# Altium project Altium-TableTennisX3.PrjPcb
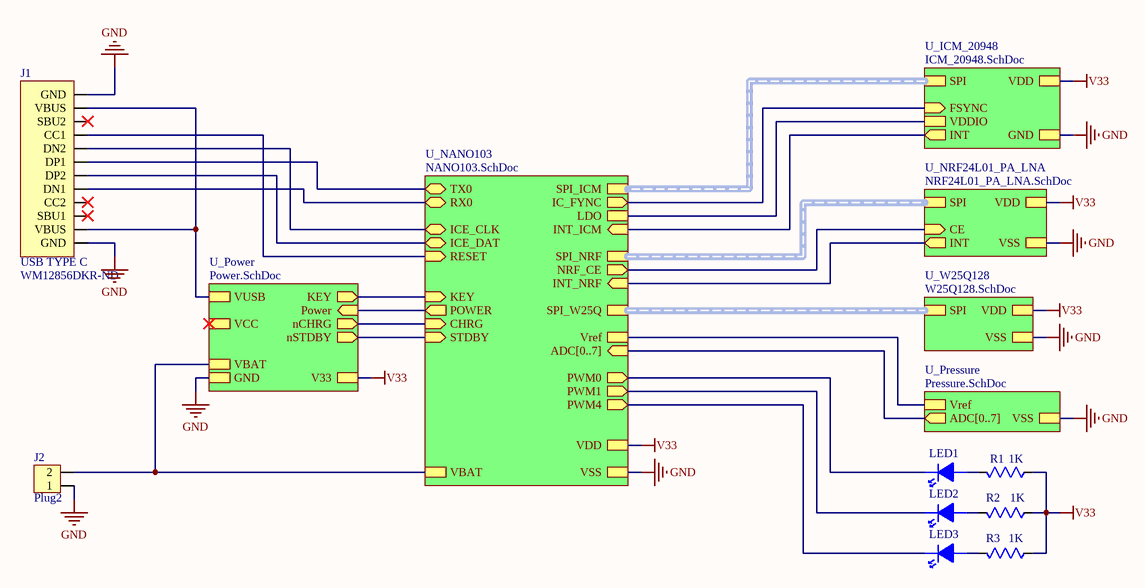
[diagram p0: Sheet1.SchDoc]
7 sheets, 62 parts. Net scope: hierarchical (ports join the sheet entries above them; power ports are global).
Board files: PCB1.PcbDoc, PCB2_bak.PcbDoc, PCB2.PcbDoc
Sheets:
  Sheet1.SchDoc
    U_Power = Power.SchDoc
    U_W25Q128 = W25Q128.SchDoc
    U_ICM_20948 = ICM_20948.SchDoc
    U_NRF24L01_PA_LNA = NRF24L01_PA_LNA.SchDoc
    U_NANO103 = NANO103.SchDoc
    U_Pressure = Pressure.SchDoc

## Sheet Sheet1.SchDoc
size A4

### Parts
J1  USB TYPE C  Supplier Part Number 1: WM12856DKR-ND  [USBC-SMD16F]
J2  Plug2  [Terminal_block_2pin_1.25mm_SMD]
LED1  LED  [SMD-0603_LED]  (value not drawn)
LED2  LED  [SMD-0603_LED]  (value not drawn)
LED3  LED  [SMD-0603_LED]  (value not drawn)
R1  value 1K  [RES_0402]  (hidden comment: Res)
R2  value 1K  [RES_0402]  (hidden comment: Res)
R3  value 1K  [RES_0402]  (hidden comment: Res)

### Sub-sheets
U_ICM_20948 = ICM_20948.SchDoc: GND, INT (out), FSYNC (in), VDD, VDDIO, SPI (harness SPI)
U_NANO103 = NANO103.SchDoc: ADC[0..7] (in), SPI_ICM (harness SPI), SPI_W25Q (harness SPI), SPI_NRF (harness SPI), INT_ICM (in), INT_NRF (in), CHRG (in), STDBY (in), KEY (in), POWER (out), TX0 (bidir), RX0 (bidir), PWM0 (out), PWM1 (out), PWM4 (out), Vref, VDD, VSS, RESET (in), NRF_CE (out), ICE_CLK (bidir), ICE_DAT (bidir), LDO, VBAT, IC_FYNC (out)
U_NRF24L01_PA_LNA = NRF24L01_PA_LNA.SchDoc: VDD, VSS, INT (out), CE (in), SPI (harness SPI)
U_Power = Power.SchDoc: VCC, KEY (out), GND, Power (in), V33, VUSB, nCHRG (out), nSTDBY (out), VBAT
U_Pressure = Pressure.SchDoc: VSS, ADC[0..7] (out), Vref
U_W25Q128 = W25Q128.SchDoc: SPI (harness SPI), VDD, VSS

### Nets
GND: J1.1(GND) J1.12(GND) J2.1 ; sheet U_Power/GND, sheet U_W25Q128/VSS, sheet U_ICM_20948/GND, sheet U_NRF24L01_PA_LNA/VSS, sheet U_NANO103/VSS, sheet U_Pressure/VSS  [project net VSS]
V33: R1.2 R2.2 R3.2 ; sheet U_Power/V33, sheet U_W25Q128/VDD, sheet U_ICM_20948/VDD, sheet U_NRF24L01_PA_LNA/VDD, sheet U_NANO103/VDD
/RESET: J1.4(CC1) ; sheet U_NANO103/RESET
CE: sheet U_NRF24L01_PA_LNA/CE, sheet U_NANO103/NRF_CE
ICE_CLK: J1.5(DN2) ; sheet U_NANO103/ICE_CLK
ICE_DAT: J1.7(DP2) ; sheet U_NANO103/ICE_DAT
INT: sheet U_NRF24L01_PA_LNA/INT, sheet U_NANO103/INT_NRF
INT1: sheet U_ICM_20948/INT, sheet U_NANO103/INT_ICM
LDO: sheet U_ICM_20948/VDDIO, sheet U_NANO103/LDO
PA12_PWM0: LED1.2 ; sheet U_NANO103/PWM0
PA13_PWM1: LED2.2 ; sheet U_NANO103/PWM1
PB11_PWM4: LED3.2 ; sheet U_NANO103/PWM4
PD6: sheet U_Power/Power, sheet U_NANO103/POWER
PD7: sheet U_Power/KEY, sheet U_NANO103/KEY
PD14: sheet U_Power/nSTDBY, sheet U_NANO103/STDBY
PD15: sheet U_Power/nCHRG, sheet U_NANO103/CHRG
PE5: sheet U_ICM_20948/FSYNC, sheet U_NANO103/IC_FYNC
RX0: J1.8(DN1) ; sheet U_NANO103/RX0
TX0: J1.6(DP1) ; sheet U_NANO103/TX0
VBAT: J2.2 ; sheet U_Power/VBAT, sheet U_NANO103/VBAT
Vref: sheet U_NANO103/Vref, sheet U_Pressure/Vref
NetC14_1: J1.2(VBUS) J1.11(VBUS) ; sheet U_Power/VUSB
NetLED1_1: LED1.1 R1.1
NetLED2_1: LED2.1 R2.1
NetLED3_1: LED3.1 R3.1

Not connected (* = marked no-connect by the designer): J1 3(SBU2)* 9(CC2)* 10(SBU1)*

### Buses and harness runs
bus sheet U_NANO103/ADC[0..7] = sheet U_Pressure/ADC[0..7]
harness sheet U_ICM_20948/SPI = sheet U_NANO103/SPI_ICM
harness sheet U_NANO103/SPI_NRF = sheet U_NRF24L01_PA_LNA/SPI
harness sheet U_NANO103/SPI_W25Q = sheet U_W25Q128/SPI

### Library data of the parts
J1 = USB TYPE C: USB Shielded I/O Receptacle; Type C; Right Angle; Surface Mount; Gold over Nickel; Manufacturer: Molex; Manufacturer Part Number: 105450-0101; Number of Contacts: 24; Current Rating: 5A; Mating Cycles: 10000; USB Standard: USB 3.1; Number of Ports: 1; Pitch: 0.5mm

## Sheet Power.SchDoc
size A4
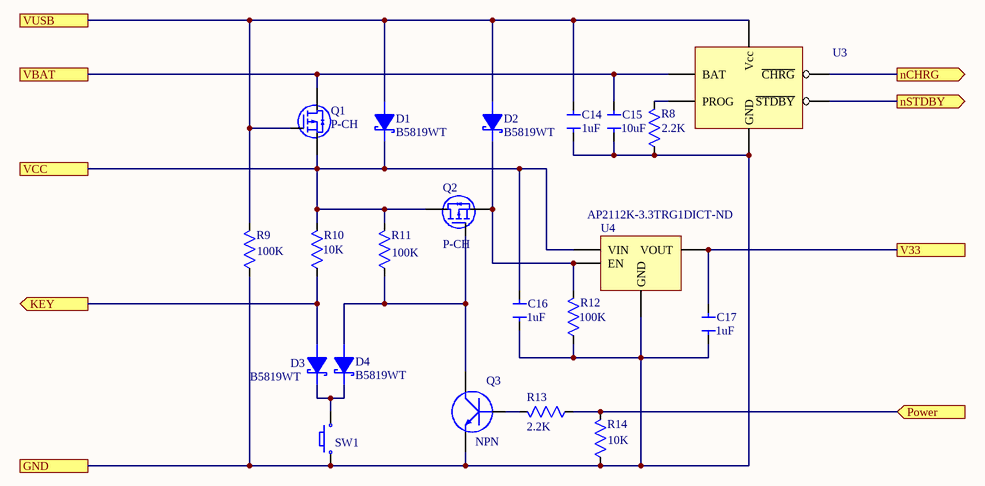
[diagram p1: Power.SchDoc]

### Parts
C14  value 1uF  [CAP_0402]  (hidden comment: Cap)
C15  value 10uF  [Cap_0603]  (hidden comment: Cap)
C16  value 1uF  [CAP_0402]  (hidden comment: Cap)
C17  value 1uF  [CAP_0402]  (hidden comment: Cap)
D1  B5819WT  [SOD-523]
D2  B5819WT  [SOD-523]
D3  B5819WT  [SOD-523]
D4  B5819WT  [SOD-523]
Q1  Polarity: P-CH  [SOT-23]  (hidden comment: SI2301DS-T1)
Q2  Polarity: P-CH  [SOT-23]  (hidden comment: SI2301DS-T1)
Q3  Polarity: NPN  [SOT-23]  (hidden comment: MMS9013L-TP)
R8  value 2.2K  [RES_0402]  (hidden comment: Res)
R9  value 100K  [RES_0402]  (hidden comment: Res)
R10  value 10K  [RES_0402]  (hidden comment: Res)
R11  value 100K  [RES_0402]  (hidden comment: Res)
R12  value 100K  [RES_0402]  (hidden comment: Res)
R13  value 2.2K  [RES_0402]  (hidden comment: Res)
R14  value 10K  [RES_0402]  (hidden comment: Res)
SW1  SPST  [ST01-111]  (value not drawn)
U3  TP4059  [SOT23-6]  (value not drawn)
U4  Supplier Part Number 1: AP2112K-3.3TRG1DICT-ND  [SOT23-5]  (hidden comment: AP2112K-3.3TRG1)

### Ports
GND, KEY (out), nCHRG (out), nSTDBY (out), Power (in), V33, VBAT, VCC, VUSB

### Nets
V33: C17.1 U4.4(VOUT) ; port V33
VSS: C14.2 C15.2 C16.2 C17.2 Q3.3 R8.2 R9.2 R12.2 R14.2 SW1.2 U3.4(GND) U4.3(GND) ; port GND
PD6: R13.2 R14.1 ; port Power
PD7: D3.1 R10.2 ; port KEY
PD14: U3.3(~{STDBY}) ; port nSTDBY
PD15: U3.2(~{CHRG}) ; port nCHRG
VBAT: C15.1 Q1.1 U3.6(BAT) ; port VBAT
NetC14_1: C14.1 D1.1 D2.1 Q1.2 R9.1 U3.1(Vcc) ; port VUSB
NetC16_1: C16.1 D1.2 Q1.3 Q2.1 R10.1 R11.1 U4.1(VIN) ; port VCC
NetD2_2: D2.2 Q2.3 R12.1 U4.2(EN)
NetD3_2: D3.2 D4.2 SW1.1
NetD4_1: D4.1 Q2.2 Q3.1 R11.2
NetQ3_2: Q3.2 R13.1
NetR8_1: R8.1 U3.5(PROG)

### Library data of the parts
D1-D4 = B5819WT: Diode Schottky 40V 1A 2-Pin SOD-523 T/R; Manufacturer: MCC; Manufacturer Part Number: B5819W-TP; Max Reverse Voltage (DC): 20V; Element Configuration: Single; Forward Voltage: 550mV; Max Forward Surge Current (Ifsm): 10A; Peak Reverse Current: 1mA; Max Power Dissipation: 250mW
Q1 Q2 = SI2301DS-T1: Trans MOSFET P-CH 20V 2.3A 3-Pin TO-236 T/R; pin to pad: 1>2 2>1; Manufacturer: Vishay Siliconix; Rise Time: 36ns; Drain to Source Resistance: 130mR; Gate to Source Voltage (Vgs): 8V; Max Power Dissipation: 1.25W; Turn-Off Delay Time: 42ns; Turn-On Delay Time: 13ns; Number of Elements: 1; Element Configuration: Single; Drain to Source Voltage (Vdss): -20V
Q3 = MMS9013L-TP: Trans GP BJT NPN 25V 0.5A 3-Pin SOT-23 T/R; pin to pad: 1>3 2>1 3>2; Manufacturer: MCC; Frequency: 150MHz; Number of Elements: 1; Collector Base Voltage (VCBO): 40V; Emitter Base Voltage (VEBO): 5V; Power Dissipation: 300mW
SW1 = Switch_Button1
U3 = TP4059: 600MA SOT23-6; pin to pad: 1>4 2>1 3>5 4>2 5>6 6>3
U4 = AP2112K-3.3TRG1: IC REG LINEAR 3.3V 600MA SOT23-5; pin to pad: 2>3 3>2 4>5; Manufacturer: Diodes; Number of Regulators: 1; Quiescent Current: 55uA; Polarity: Positive; Max Input Voltage: 6V; Min Input Voltage: 2.5V; Accuracy: 1.5%; Dropout Voltage: 250mV; Output Type: Fixed

## Sheet W25Q128.SchDoc
size A4
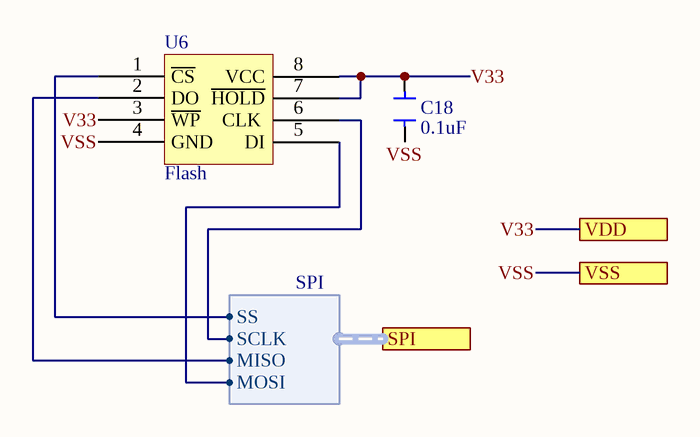
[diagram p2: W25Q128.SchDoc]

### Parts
C18  value 0.1uF  [CAP_0402]  (hidden comment: Cap)
U6  Flash  [8-Pin SOIC 208-mil]

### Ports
SPI (harness SPI), VDD, VSS

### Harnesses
SPI: SS, MISO, MOSI, SCLK

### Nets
V33: C18.1 U6.3(~{WP}) U6.7(~{HOLD}) U6.8(VCC) ; port VDD
VSS: C18.2 U6.4(GND) ; port VSS
SPI1_MISO: U6.2(DO) ; port SPI.MISO
SPI1_MOSI: U6.5(DI) ; port SPI.MOSI
SPI1_SCLK: U6.6(CLK) ; port SPI.SCLK
SPI1_SS: U6.1(~{CS}) ; port SPI.SS

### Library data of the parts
U6 = W25QXX

## Sheet ICM_20948.SchDoc
size A4
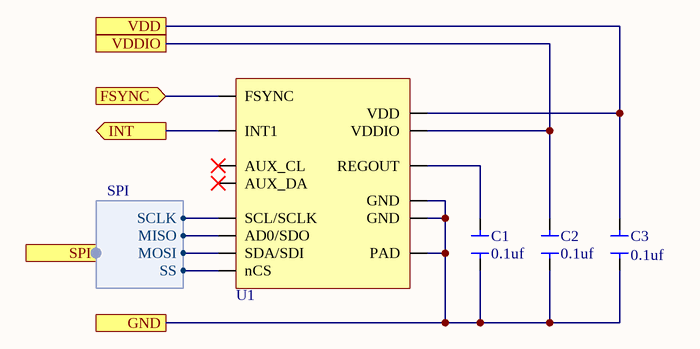
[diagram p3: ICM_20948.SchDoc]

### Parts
C1  value 0.1uf  [CAP_0402]  (hidden comment: Cap)
C2  value 0.1uf  [CAP_0402]  (hidden comment: Cap)
C3  value 0.1uf  [CAP_0402]  (hidden comment: Cap)
U1  ICM-20948  [QFN_24_3X3]  (value not drawn)

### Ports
FSYNC (in), GND, INT (out), SPI (harness SPI), VDD, VDDIO

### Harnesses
SPI: SS, SCLK, MISO, MOSI

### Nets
V33: C3.1 U1.13(VDD) ; port VDD
VSS: C1.2 C2.2 C3.2 U1.18(GND) U1.20(GND) U1.25(PAD) ; port GND
INT1: U1.12(INT1) ; port INT
LDO: C2.1 U1.8(VDDIO) ; port VDDIO
PE5: U1.11(FSYNC) ; port FSYNC
SPI0_MISO: U1.9(AD0/SDO) ; port SPI.MISO
SPI0_MOSI: U1.24(SDA/SDI) ; port SPI.MOSI
SPI0_SCLK: U1.23(SCL/SCLK) ; port SPI.SCLK
SPI0_SS: U1.22(nCS) ; port SPI.SS
NetC1_1: C1.1 U1.10(REGOUT)

Not connected (* = marked no-connect by the designer): U1 7(AUX_CL)* 21(AUX_DA)*

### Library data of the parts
U1 = ICM-20948: Accelerometer, Gyroscope, Magnetometer, 9 Axis Sensor IÂ²C, SPI Output; MF: TDK InvenSense

## Sheet NRF24L01_PA_LNA.SchDoc
size A4
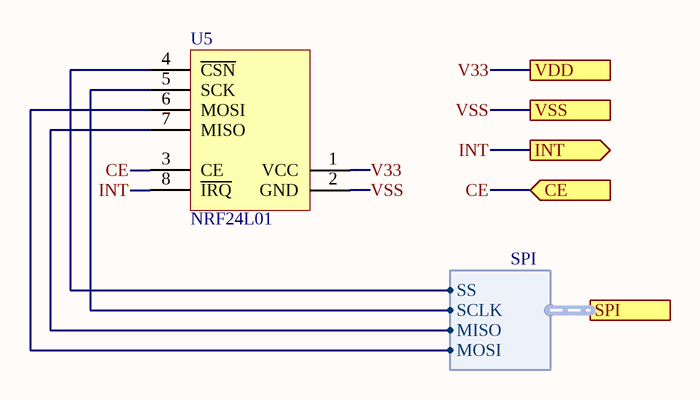
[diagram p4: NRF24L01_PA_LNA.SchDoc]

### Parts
U5  NRF24L01  [NRF24L01P+PA+LNA+IPX]

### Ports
CE (in), INT (out), SPI (harness SPI), VDD, VSS

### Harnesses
SPI: SS, MISO, MOSI, SCLK

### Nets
V33: U5.1(VCC) ; port VDD
VSS: U5.2(GND) ; port VSS
CE: U5.3(CE) ; port CE
INT: U5.8(~{IRQ}) ; port INT
SPI2_MISO: U5.7(MISO) ; port SPI.MISO
SPI2_MOSI: U5.6(MOSI) ; port SPI.MOSI
SPI2_SCLK: U5.5(SCK) ; port SPI.SCLK
SPI2_SS: U5.4(~{CSN}) ; port SPI.SS

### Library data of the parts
U5 = NRF24L01_module: pin to pad: 2>8 3>2 4>3 5>4 6>5 7>6 8>7

## Sheet NANO103.SchDoc
size A3
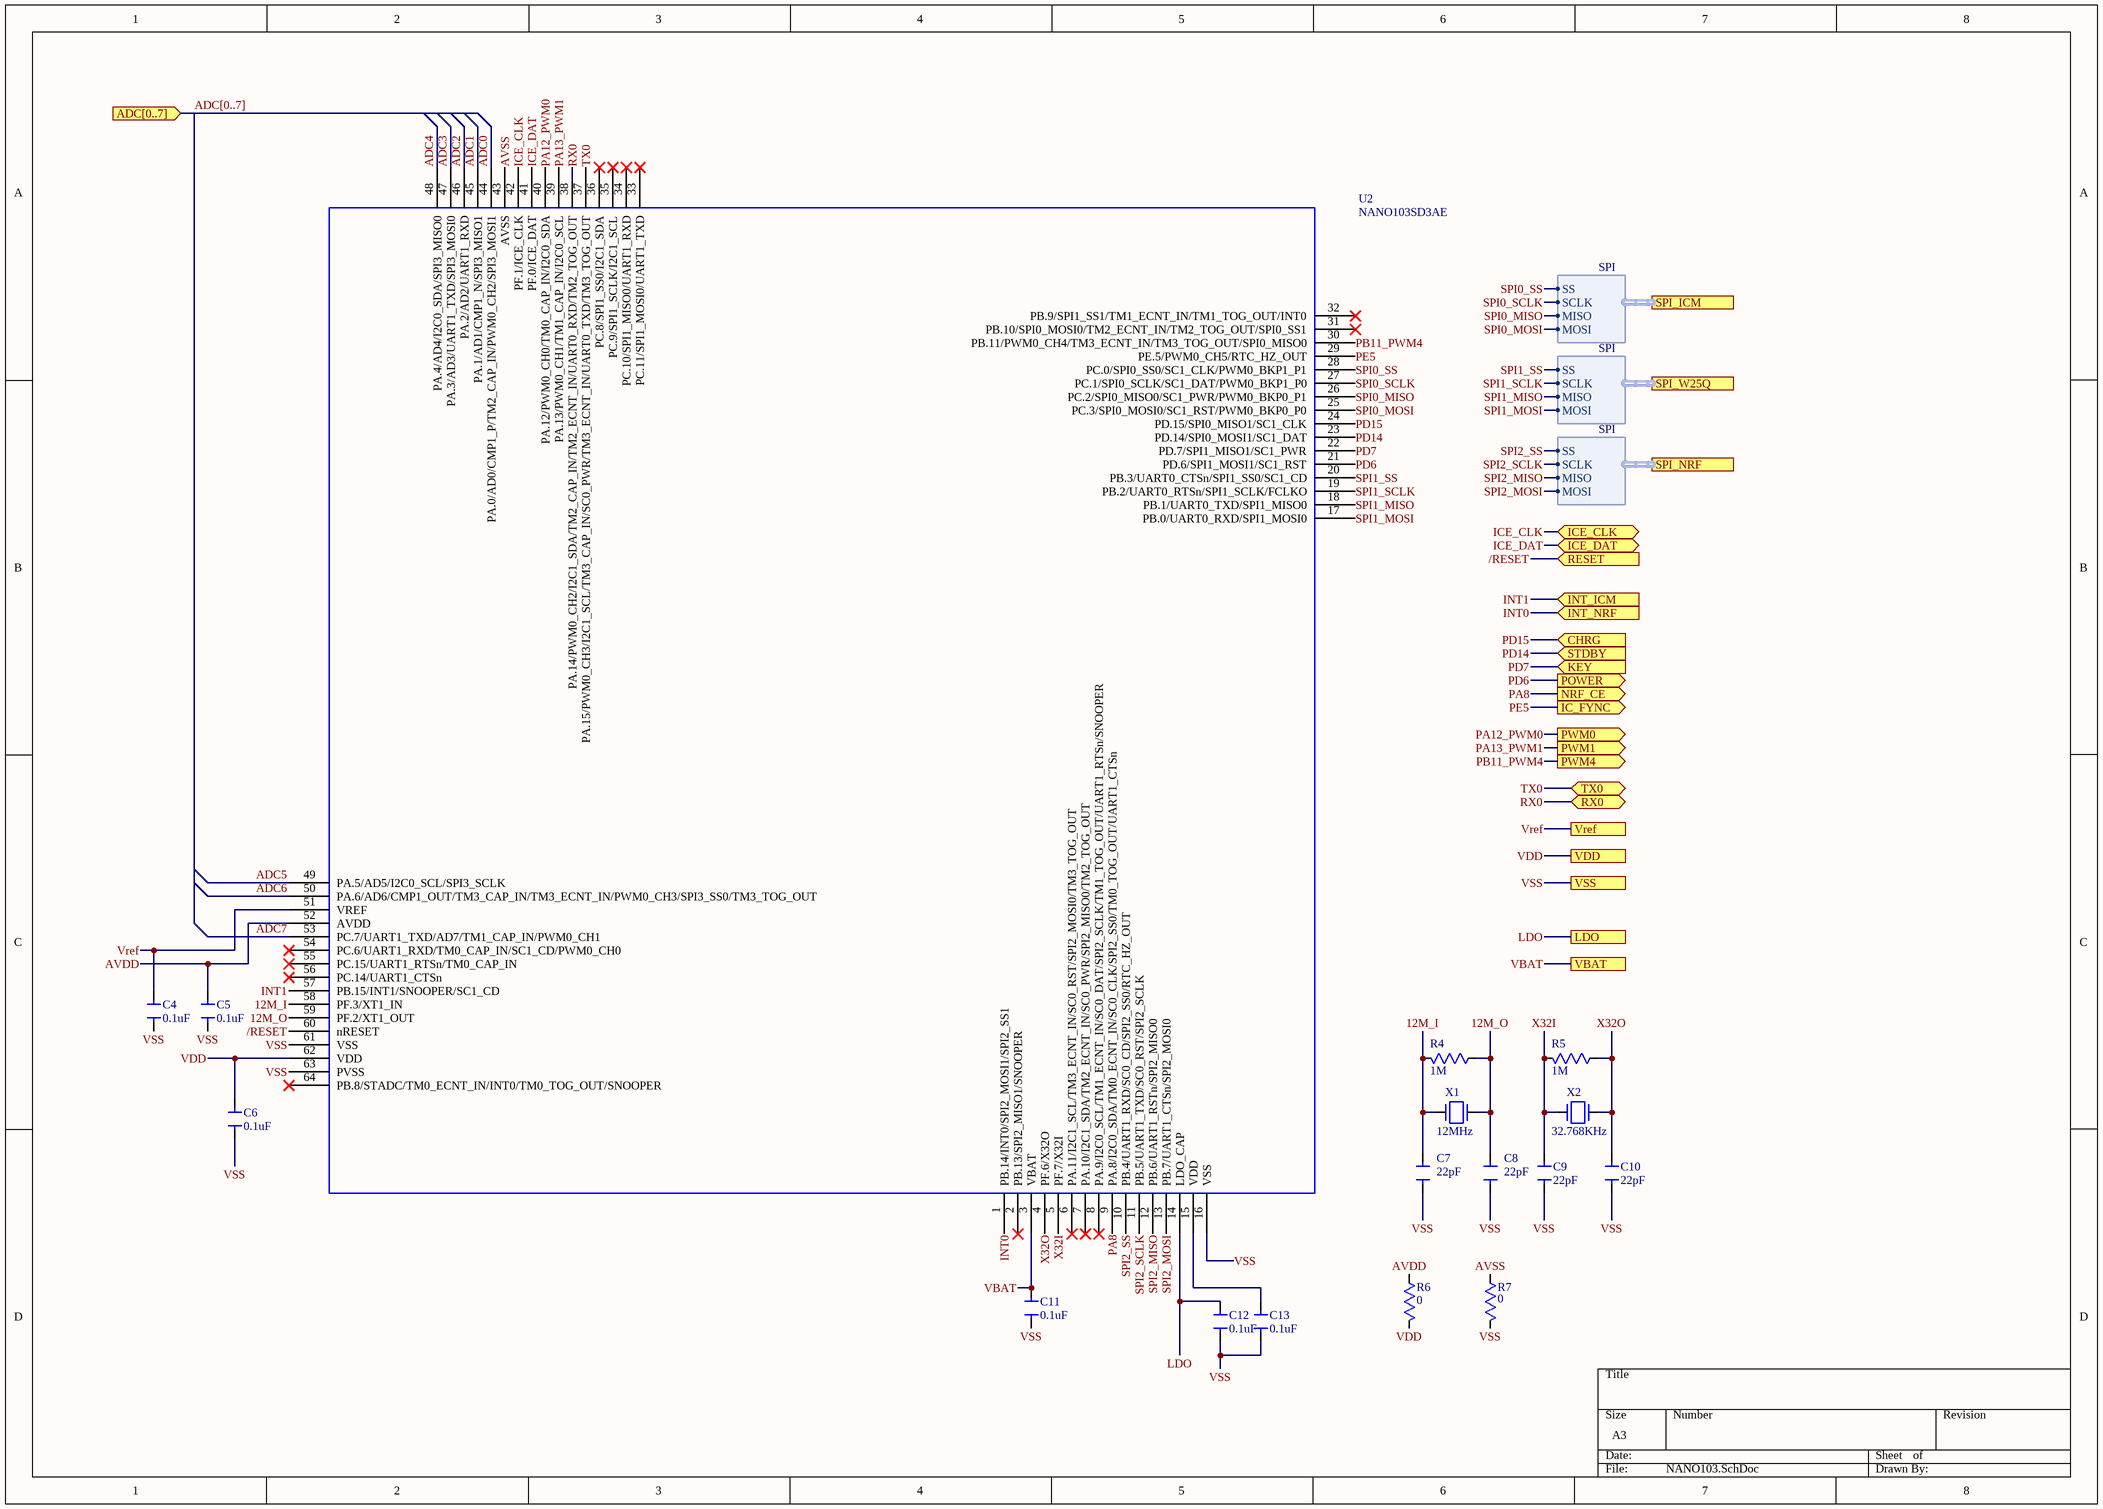
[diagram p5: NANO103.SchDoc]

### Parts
C4  value 0.1uF  [CAP_0402]  (hidden comment: Cap)
C5  value 0.1uF  [CAP_0402]  (hidden comment: Cap)
C6  value 0.1uF  [CAP_0402]  (hidden comment: Cap)
C7  value 22pF  [CAP_0402]  (hidden comment: Cap)
C8  value 22pF  [CAP_0402]  (hidden comment: Cap)
C9  value 22pF  [CAP_0402]  (hidden comment: Cap)
C10  value 22pF  [CAP_0402]  (hidden comment: Cap)
C11  value 0.1uF  [CAP_0402]  (hidden comment: Cap)
C12  value 0.1uF  [CAP_0402]  (hidden comment: Cap)
C13  value 0.1uF  [CAP_0402]  (hidden comment: Cap)
R4  value 1M  [RES_0402]  (hidden comment: Res)
R5  value 1M  [RES_0402]  (hidden comment: Res)
R6  value 0  [RES_0402]  (hidden comment: Res)
R7  value 0  [RES_0402]  (hidden comment: Res)
U2  NANO103SD3AE  [MCU_LQFP_64_7x7]
X1  value 12MHz  [2520S]  (hidden comment: Xtal)
X2  value 32.768KHz  [FC-135]  (hidden comment: Xtal)

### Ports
ADC[0..7] (in), CHRG (in), IC_FYNC (out), ICE_CLK (bidir), ICE_DAT (bidir), INT_ICM (in), INT_NRF (in), KEY (in), LDO, NRF_CE (out), POWER (out), PWM0 (out), PWM1 (out), PWM4 (out), RESET (in), RX0 (bidir), SPI_ICM (harness SPI), SPI_NRF (harness SPI), SPI_W25Q (harness SPI), STDBY (in), TX0 (bidir), VBAT, VDD, Vref, VSS

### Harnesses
SPI: SS, MISO, MOSI, SCLK

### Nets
VDD: C6.2 R6.1 U2.62(VDD) ; port VDD  [project net V33]
VSS: C4.1 C5.1 C6.1 C7.2 C8.2 C9.2 C10.2 C11.1 C12.1 C13.1 R7.1 U2.16(VSS) U2.61(VSS) U2.63(PVSS) ; port VSS
12M_I: C7.1 R4.1 U2.58(PF.3/XT1_IN) X1.2
12M_O: C8.1 R4.2 U2.59(PF.2/XT1_OUT) X1.1
/RESET: U2.60(nRESET) ; port RESET
ADC0: U2.44(PA.0/AD0/CMP1_P/TM2_CAP_IN/PWM0_CH2/SPI3_MOSI1)
ADC1: U2.45(PA.1/AD1/CMP1_N/SPI3_MISO1)
ADC2: U2.46(PA.2/AD2/UART1_RXD)
ADC3: U2.47(PA.3/AD3/UART1_TXD/SPI3_MOSI0)
ADC4: U2.48(PA.4/AD4/I2C0_SDA/SPI3_MISO0)
ADC5: U2.49(PA.5/AD5/I2C0_SCL/SPI3_SCLK)
ADC6: U2.50(PA.6/AD6/CMP1_OUT/TM3_CAP_IN/TM3_ECNT_IN/PWM0_CH3/SPI3_SS0/TM3_TOG_OUT)
ADC7: U2.53(PC.7/UART1_TXD/AD7/TM1_CAP_IN/PWM0_CH1)
AVDD: C5.2 R6.2 U2.52(AVDD)
AVSS: R7.2 U2.43(AVSS)
ICE_CLK: U2.42(PF.1/ICE_CLK) ; port ICE_CLK
ICE_DAT: U2.41(PF.0/ICE_DAT) ; port ICE_DAT
INT0: U2.1(PB.14/INT0/SPI2_MOSI1/SPI2_SS1) ; port INT_NRF  [project net INT]
INT1: U2.57(PB.15/INT1/SNOOPER/SC1_CD) ; port INT_ICM
LDO: C12.2 U2.14(LDO_CAP) ; port LDO
PA8: U2.9(PA.8/I2C0_SDA/TM0_ECNT_IN/SC0_CLK/SPI2_SS0/TM0_TOG_OUT/UART1_CTSn) ; port NRF_CE  [project net CE]
PA12_PWM0: U2.40(PA.12/PWM0_CH0/TM0_CAP_IN/I2C0_SDA) ; port PWM0
PA13_PWM1: U2.39(PA.13/PWM0_CH1/TM1_CAP_IN/I2C0_SCL) ; port PWM1
PB11_PWM4: U2.30(PB.11/PWM0_CH4/TM3_ECNT_IN/TM3_TOG_OUT/SPI0_MISO0) ; port PWM4
PD6: U2.21(PD.6/SPI1_MOSI1/SC1_RST) ; port POWER
PD7: U2.22(PD.7/SPI1_MISO1/SC1_PWR) ; port KEY
PD14: U2.23(PD.14/SPI0_MOSI1/SC1_DAT) ; port STDBY
PD15: U2.24(PD.15/SPI0_MISO1/SC1_CLK) ; port CHRG
PE5: U2.29(PE.5/PWM0_CH5/RTC_HZ_OUT) ; port IC_FYNC
RX0: U2.38(PA.14/PWM0_CH2/I2C1_SDA/TM2_CAP_IN/TM2_ECNT_IN/UART0_RXD/TM2_TOG_OUT) ; port RX0
SPI0_MISO: U2.26(PC.2/SPI0_MISO0/SC1_PWR/PWM0_BKP0_P1) ; port SPI_ICM.MISO
SPI0_MOSI: U2.25(PC.3/SPI0_MOSI0/SC1_RST/PWM0_BKP0_P0) ; port SPI_ICM.MOSI
SPI0_SCLK: U2.27(PC.1/SPI0_SCLK/SC1_DAT/PWM0_BKP1_P0) ; port SPI_ICM.SCLK
SPI0_SS: U2.28(PC.0/SPI0_SS0/SC1_CLK/PWM0_BKP1_P1) ; port SPI_ICM.SS
SPI1_MISO: U2.18(PB.1/UART0_TXD/SPI1_MISO0) ; port SPI_W25Q.MISO
SPI1_MOSI: U2.17(PB.0/UART0_RXD/SPI1_MOSI0) ; port SPI_W25Q.MOSI
SPI1_SCLK: U2.19(PB.2/UART0_RTSn/SPI1_SCLK/FCLKO) ; port SPI_W25Q.SCLK
SPI1_SS: U2.20(PB.3/UART0_CTSn/SPI1_SS0/SC1_CD) ; port SPI_W25Q.SS
SPI2_MISO: U2.12(PB.6/UART1_RSTn/SPI2_MISO0) ; port SPI_NRF.MISO
SPI2_MOSI: U2.13(PB.7/UART1_CTSn/SPI2_MOSI0) ; port SPI_NRF.MOSI
SPI2_SCLK: U2.11(PB.5/UART1_TXD/SC0_RST/SPI2_SCLK) ; port SPI_NRF.SCLK
SPI2_SS: U2.10(PB.4/UART1_RXD/SC0_CD/SPI2_SS0/RTC_HZ_OUT) ; port SPI_NRF.SS
TX0: U2.37(PA.15/PWM0_CH3/I2C1_SCL/TM3_CAP_IN/SC0_PWR/TM3_ECNT_IN/UART0_TXD/TM3_TOG_OUT) ; port TX0
VBAT: C11.2 U2.3(VBAT) ; port VBAT
Vref: C4.2 U2.51(VREF) ; port Vref
X32I: C9.1 R5.1 U2.5(PF.7/X32I) X2.2
X32O: C10.1 R5.2 U2.4(PF.6/X32O) X2.1
NetC13_2: C13.2 U2.15(VDD)

Not connected (* = marked no-connect by the designer): U2 2(PB.13/SPI2_MISO1/SNOOPER)* 6(PA.11/I2C1_SCL/TM3_ECNT_IN/SC0_RST/SPI2_MOSI0/TM3_TOG_OUT)* 7(PA.10/I2C1_SDA/TM2_ECNT_IN/SC0_PWR/SPI2_MISO0/TM2_TOG_OUT)* 8(PA.9/I2C0_SCL/TM1_ECNT_IN/SC0_DAT/SPI2_SCLK/TM1_TOG_OUT/UART1_RTSn/SNOOPER)* 31(PB.10/SPI0_MOSI0/TM2_ECNT_IN/TM2_TOG_OUT/SPI0_SS1)* 32(PB.9/SPI1_SS1/TM1_ECNT_IN/TM1_TOG_OUT/INT0)* 33(PC.11/SPI1_MOSI0/UART1_TXD)* 34(PC.10/SPI1_MISO0/UART1_RXD)* 35(PC.9/SPI1_SCLK/I2C1_SCL)* 36(PC.8/SPI1_SS0/I2C1_SDA)* 54(PC.6/UART1_RXD/TM0_CAP_IN/SC1_CD/PWM0_CH0)* 55(PC.15/UART1_RTSn/TM0_CAP_IN)* 56(PC.14/UART1_CTSn)* 64(PB.8/STADC/TM0_ECNT_IN/INT0/TM0_TOG_OUT/SNOOPER)*

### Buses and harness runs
bus ADC[0..7] = port ADC[0..7]

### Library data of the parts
U2 = NANO103SD3AE: OriginalSymbolOrigin: (0,0)

## Sheet Pressure.SchDoc
size A4
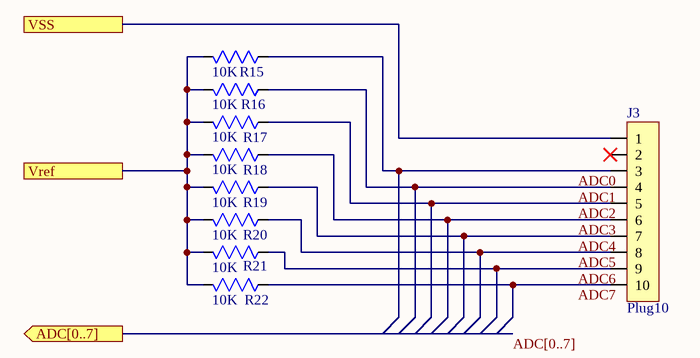
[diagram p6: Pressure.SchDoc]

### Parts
J3  Plug10  [FPC0.5-10PS]
R15  value 10K  [RES_0402]  (hidden comment: Res)
R16  value 10K  [RES_0402]  (hidden comment: Res)
R17  value 10K  [RES_0402]  (hidden comment: Res)
R18  value 10K  [RES_0402]  (hidden comment: Res)
R19  value 10K  [RES_0402]  (hidden comment: Res)
R20  value 10K  [RES_0402]  (hidden comment: Res)
R21  value 10K  [RES_0402]  (hidden comment: Res)
R22  value 10K  [RES_0402]  (hidden comment: Res)

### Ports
ADC[0..7] (out), Vref, VSS

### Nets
VSS: J3.1 ; port VSS
ADC0: J3.3 R15.2
ADC1: J3.4 R16.2
ADC2: J3.5 R17.2
ADC3: J3.6 R18.2
ADC4: J3.7 R19.2
ADC5: J3.8 R20.2
ADC6: J3.9 R21.2
ADC7: J3.10 R22.2
Vref: R15.1 R16.1 R17.1 R18.1 R19.1 R20.1 R21.1 R22.1 ; port Vref

Not connected (* = marked no-connect by the designer): J3 2*

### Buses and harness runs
bus ADC[0..7] = port ADC[0..7]

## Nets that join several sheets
V33: Sheet1 (R1.2 R2.2 R3.2), Power (C17.1 U4.4), W25Q128 (C18.1 U6.3 U6.7 U6.8), ICM_20948 (C3.1 U1.13), NRF24L01_PA_LNA (U5.1), NANO103 (C6.2 R6.1 U2.62)
VSS: Sheet1 (J1.1 J1.12 J2.1), Power (12 pins), W25Q128 (C18.2 U6.4), ICM_20948 (6 pins), NRF24L01_PA_LNA (U5.2), NANO103 (14 pins), Pressure (J3.1)
/RESET: Sheet1 (J1.4), NANO103 (U2.60)
ADC0: NANO103 (U2.44), Pressure (J3.3 R15.2)
ADC1: NANO103 (U2.45), Pressure (J3.4 R16.2)
ADC2: NANO103 (U2.46), Pressure (J3.5 R17.2)
ADC3: NANO103 (U2.47), Pressure (J3.6 R18.2)
ADC4: NANO103 (U2.48), Pressure (J3.7 R19.2)
ADC5: NANO103 (U2.49), Pressure (J3.8 R20.2)
ADC6: NANO103 (U2.50), Pressure (J3.9 R21.2)
ADC7: NANO103 (U2.53), Pressure (J3.10 R22.2)
CE: NRF24L01_PA_LNA (U5.3), NANO103 (U2.9)
ICE_CLK: Sheet1 (J1.5), NANO103 (U2.42)
ICE_DAT: Sheet1 (J1.7), NANO103 (U2.41)
INT: NRF24L01_PA_LNA (U5.8), NANO103 (U2.1)
INT1: ICM_20948 (U1.12), NANO103 (U2.57)
LDO: ICM_20948 (C2.1 U1.8), NANO103 (C12.2 U2.14)
NetC14_1: Sheet1 (J1.2 J1.11), Power (6 pins)
PA12_PWM0: Sheet1 (LED1.2), NANO103 (U2.40)
PA13_PWM1: Sheet1 (LED2.2), NANO103 (U2.39)
PB11_PWM4: Sheet1 (LED3.2), NANO103 (U2.30)
PD6: Power (R13.2 R14.1), NANO103 (U2.21)
PD7: Power (D3.1 R10.2), NANO103 (U2.22)
PD14: Power (U3.3), NANO103 (U2.23)
PD15: Power (U3.2), NANO103 (U2.24)
PE5: ICM_20948 (U1.11), NANO103 (U2.29)
RX0: Sheet1 (J1.8), NANO103 (U2.38)
SPI0_MISO: ICM_20948 (U1.9), NANO103 (U2.26)
SPI0_MOSI: ICM_20948 (U1.24), NANO103 (U2.25)
SPI0_SCLK: ICM_20948 (U1.23), NANO103 (U2.27)
SPI0_SS: ICM_20948 (U1.22), NANO103 (U2.28)
SPI1_MISO: W25Q128 (U6.2), NANO103 (U2.18)
SPI1_MOSI: W25Q128 (U6.5), NANO103 (U2.17)
SPI1_SCLK: W25Q128 (U6.6), NANO103 (U2.19)
SPI1_SS: W25Q128 (U6.1), NANO103 (U2.20)
SPI2_MISO: NRF24L01_PA_LNA (U5.7), NANO103 (U2.12)
SPI2_MOSI: NRF24L01_PA_LNA (U5.6), NANO103 (U2.13)
SPI2_SCLK: NRF24L01_PA_LNA (U5.5), NANO103 (U2.11)
SPI2_SS: NRF24L01_PA_LNA (U5.4), NANO103 (U2.10)
TX0: Sheet1 (J1.6), NANO103 (U2.37)
VBAT: Sheet1 (J2.2), Power (C15.1 Q1.1 U3.6), NANO103 (C11.2 U2.3)
Vref: NANO103 (C4.2 U2.51), Pressure (8 pins)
